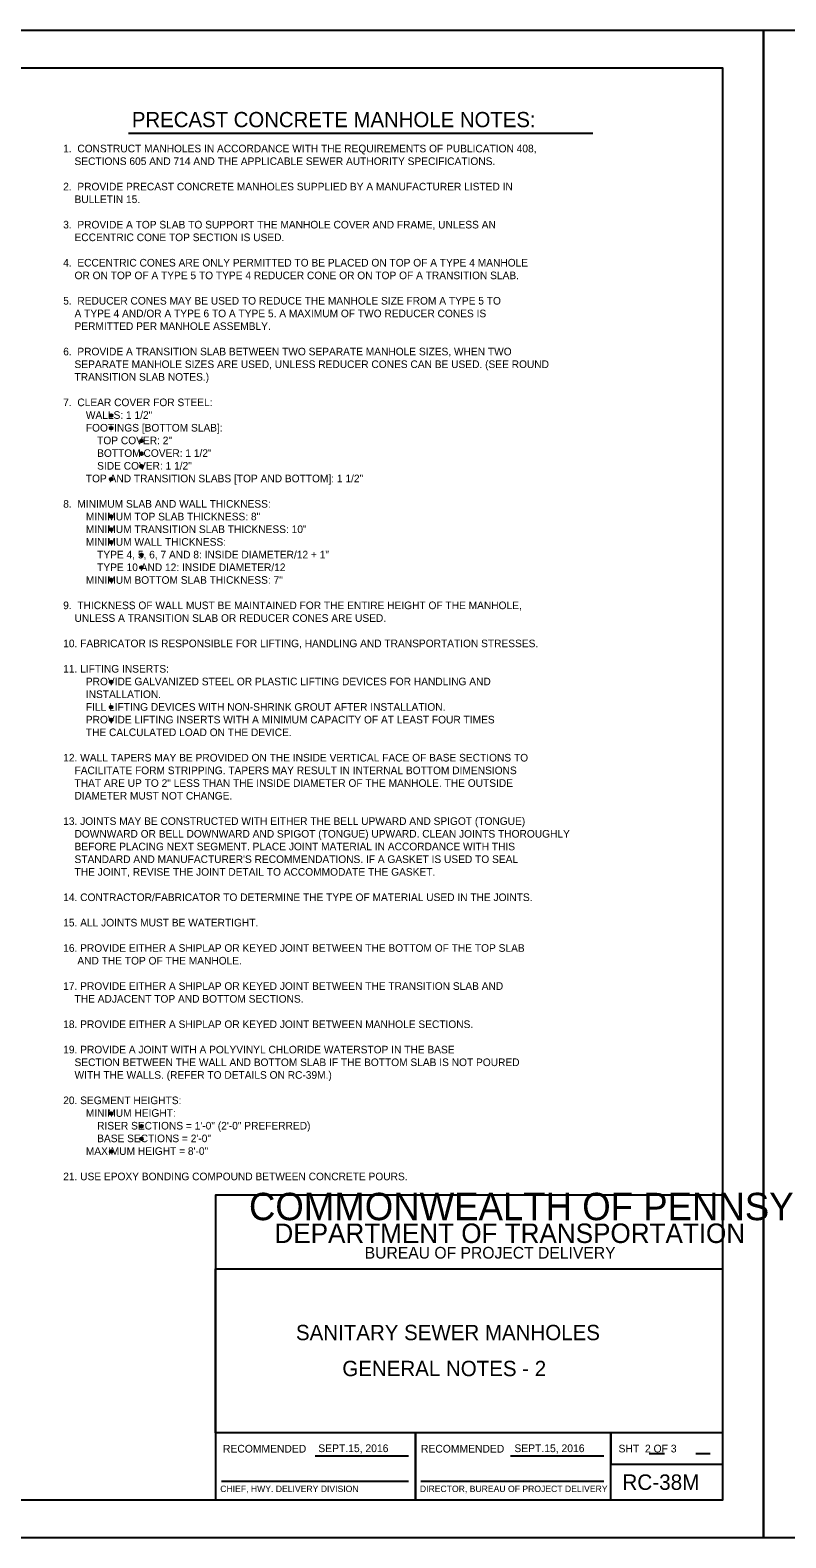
# Model space of a CAD drawing. Extents: x 2106427 to 2114911, y 988717 to 990787.
# Drawn here: x 2110996 to 2111974, y 988839 to 990787 of the extents above; entities that cross this region are included whole.
import ezdxf

# ---------------------------------------------------------------- set-up
doc = ezdxf.new("R2010")
doc.units = 0
for name, color, linetype in [('1', 7, 'Continuous'), ('2', 7, 'Continuous'), ('3', 7, 'Continuous'), ('PLT-BNDY', 7, 'Continuous')]:
    doc.layers.add(name, color=color, linetype=linetype)

msp = doc.modelspace()

# ---------------------------------------------------------------- linework, layer by layer
at = {"layer": '1'}
for p, q in [((2111123.6, 990654.3), (2111724.2, 990654.3)), ((2111365.2, 988944.7), (2111485.6, 988944.7)), ((2111617.8, 988944.7), (2111738.2, 988944.7)), ((2111796.9, 988947.4), (2111817, 988947.4)), ((2111857.3, 988947.4), (2111876.1, 988947.4)), ((2111244.1, 988911.7), (2111485.6, 988911.7)), ((2111501.7, 988911.7), (2111738.2, 988911.7))]:
    msp.add_line(p, q, dxfattribs=at)
msp.add_lwpolyline([(2111892.4, 988887.7), (2111892.4, 990738.1), (2109313.6, 990738.1), (2109313.6, 988887.7), (2111892.4, 988887.7), (2111892.4, 988974.2), (2111236.2, 988974.2), (2111236.2, 989186.4), (2111892.4, 989186.4), (2111892.4, 989281.4), (2111236.2, 989281.4), (2111236.2, 988887.7), (2111494.8, 988887.7), (2111494.8, 988974.2), (2111494.8, 988887.7), (2111747.4, 988887.7), (2111747.4, 988974.2), (2111747.4, 988933.8), (2111892.4, 988933.8)], dxfattribs=at)
for centre, radius in [((2111101.3, 990289.1), 1.75), ((2111101.3, 990272.7), 1.75), ((2111101.3, 990289.1), 1.31), ((2111101.3, 990272.7), 1.31), ((2111101.3, 990289.1), 0.875), ((2111101.3, 990272.7), 0.875), ((2111101.3, 990289.1), 0.437), ((2111101.3, 990272.7), 0.437), ((2111140.4, 990256.3), 1.75), ((2111140.4, 990256.3), 1.31), ((2111140.4, 990256.3), 0.875), ((2111140.4, 990256.3), 0.437), ((2111140.4, 990239.9), 1.75), ((2111140.4, 990239.9), 1.31), ((2111140.4, 990239.9), 0.875), ((2111140.4, 990239.9), 0.437), ((2111140.4, 990223.5), 1.75), ((2111140.4, 990223.5), 1.31), ((2111140.4, 990223.5), 0.875), ((2111140.4, 990223.5), 0.437), ((2111101.3, 990207), 1.75), ((2111101.3, 990207), 1.31), ((2111101.3, 990207), 0.875), ((2111101.3, 990207), 0.437), ((2111101.3, 990158.5), 1.75), ((2111101.3, 990158.5), 1.31), ((2111101.3, 990158.5), 0.875), ((2111101.3, 990158.5), 0.437), ((2111101.3, 990141.8), 1.75), ((2111101.3, 990141.8), 1.31), ((2111101.3, 990141.8), 0.875), ((2111101.3, 990141.8), 0.437), ((2111101.3, 990125.4), 1.75), ((2111101.3, 990125.4), 1.31), ((2111101.3, 990125.4), 0.875), ((2111101.3, 990125.4), 0.437), ((2111140.4, 990108.9), 1.75), ((2111140.4, 990108.9), 1.31), ((2111140.4, 990108.9), 0.875), ((2111140.4, 990108.9), 0.437), ((2111101.3, 990076.6), 1.75), ((2111140.4, 990092.6), 1.75), ((2111140.4, 990092.6), 1.31), ((2111140.4, 990092.6), 0.875), ((2111140.4, 990092.6), 0.437), ((2111101.3, 990076.6), 1.31), ((2111101.3, 990076.6), 0.875), ((2111101.3, 990076.6), 0.437), ((2111101.3, 989945.1), 1.75), ((2111101.3, 989945.1), 1.31), ((2111101.3, 989945.1), 0.875), ((2111101.3, 989945.1), 0.437), ((2111101.3, 989912.3), 1.75), ((2111101.3, 989912.3), 1.31), ((2111101.3, 989912.3), 0.875), ((2111101.3, 989912.3), 0.437), ((2111101.3, 989895.9), 1.75), ((2111101.3, 989895.9), 1.31), ((2111101.3, 989895.9), 0.875), ((2111101.3, 989895.9), 0.437), ((2111101.3, 989386.9), 1.75), ((2111101.3, 989386.9), 1.31), ((2111101.3, 989386.9), 0.875), ((2111101.3, 989386.9), 0.437), ((2111140.4, 989370.7), 1.75), ((2111140.4, 989370.7), 1.31), ((2111140.4, 989370.7), 0.875), ((2111140.4, 989370.7), 0.437), ((2111101.3, 989337.7), 1.75), ((2111101.3, 989337.7), 1.31), ((2111101.3, 989337.7), 0.875), ((2111101.3, 989337.7), 0.437), ((2111140.4, 989354.1), 1.75), ((2111140.4, 989354.1), 1.31), ((2111140.4, 989354.1), 0.875), ((2111140.4, 989354.1), 0.437)]:
    msp.add_circle(centre, radius, dxfattribs=at)
at = {"layer": 'PLT-BNDY'}
for points in [[(2109185.7, 990787.3), (2111944.9, 990787.3), (2111944.9, 988838.5), (2109185.7, 988838.5)], [(2111944.9, 990787.3), (2114704.1, 990787.3), (2114704.1, 988838.5), (2111944.9, 988838.5)]]:
    msp.add_lwpolyline(points, close=True, dxfattribs=at)

# ---------------------------------------------------------------- texts
at = {"layer": '1'}
msp.add_text('SANITARY SEWER MANHOLES', height=19.816, dxfattribs=at).set_placement((2111340.2, 989094))
at = {"layer": '2'}
msp.add_text('GENERAL NOTES - 2', height=19.816, dxfattribs=at).set_placement((2111400.2, 989047.5))
at = {"layer": '3'}
for s, height, p in [('PRECAST CONCRETE MANHOLE NOTES:', 19.685, (2111128, 990661.9)), ('1.  CONSTRUCT MANHOLES IN ACCORDANCE WITH THE REQUIREMENTS OF PUBLICATION 408,', 9.843, (2111039.2, 990629.4)), ('    SECTIONS 605 AND 714 AND THE APPLICABLE SEWER AUTHORITY SPECIFICATIONS. ', 9.843, (2111039.2, 990613)), ('2.  PROVIDE PRECAST CONCRETE MANHOLES SUPPLIED BY A MANUFACTURER LISTED IN', 9.843, (2111039.2, 990580.2)), ('    BULLETIN 15.', 9.843, (2111039.2, 990563.8)), ('3.  PROVIDE A TOP SLAB TO SUPPORT THE MANHOLE COVER AND FRAME, UNLESS AN', 9.843, (2111039.2, 990531)), ('    ECCENTRIC CONE TOP SECTION IS USED.', 9.843, (2111039.2, 990514.6)), ('4.  ECCENTRIC CONES ARE ONLY PERMITTED TO BE PLACED ON TOP OF A TYPE 4 MANHOLE', 9.843, (2111039.2, 990481.8)), ('    OR ON TOP OF A TYPE 5 TO TYPE 4 REDUCER CONE OR ON TOP OF A TRANSITION SLAB.', 9.843, (2111039.2, 990465.4)), ('5.  REDUCER CONES MAY BE USED TO REDUCE THE MANHOLE SIZE FROM A TYPE 5 TO', 9.843, (2111039.2, 990432.6)), ('    A TYPE 4 AND/OR A TYPE 6 TO A TYPE 5. A MAXIMUM OF TWO REDUCER CONES IS', 9.843, (2111039.2, 990416.2)), ('    PERMITTED PER MANHOLE ASSEMBLY.', 9.843, (2111039.2, 990399.8)), ('6.  PROVIDE A TRANSITION SLAB BETWEEN TWO SEPARATE MANHOLE SIZES, WHEN TWO', 9.843, (2111039.2, 990367)), ('    SEPARATE MANHOLE SIZES ARE USED, UNLESS REDUCER CONES CAN BE USED. (SEE ROUND', 9.843, (2111039.2, 990350.6)), ('    TRANSITION SLAB NOTES.) ', 9.843, (2111039.2, 990334.2)), ('7.  CLEAR COVER FOR STEEL:', 9.843, (2111039.2, 990301.3)), ('        WALLS: 1 1/2"', 9.843, (2111039.2, 990284.9)), ('        FOOTINGS [BOTTOM SLAB]:', 9.843, (2111039.2, 990268.5)), ('            TOP COVER: 2"', 9.843, (2111039.2, 990252.1)), ('            BOTTOM COVER: 1 1/2"', 9.843, (2111039.2, 990235.7)), ('            SIDE COVER: 1 1/2"', 9.843, (2111039.2, 990219.3)), ('        TOP AND TRANSITION SLABS [TOP AND BOTTOM]: 1 1/2"', 9.843, (2111039.2, 990202.9)), ('8.  MINIMUM SLAB AND WALL THICKNESS:', 9.843, (2111039.2, 990170.1)), ('        MINIMUM TOP SLAB THICKNESS: 8"', 9.843, (2111039.2, 990153.7)), ('        MINIMUM TRANSITION SLAB THICKNESS: 10"', 9.843, (2111039.2, 990137.3)), ('        MINIMUM WALL THICKNESS:', 9.843, (2111039.2, 990120.9)), ('            TYPE 4, 5, 6, 7 AND 8: INSIDE DIAMETER/12 + 1"', 9.843, (2111039.2, 990104.5)), ('            TYPE 10 AND 12: INSIDE DIAMETER/12', 9.843, (2111039.2, 990088.1)), ('        MINIMUM BOTTOM SLAB THICKNESS: 7"', 9.843, (2111039.2, 990071.7)), ('9.  THICKNESS OF WALL MUST BE MAINTAINED FOR THE ENTIRE HEIGHT OF THE MANHOLE,', 9.843, (2111039.2, 990038.9)), ('    UNLESS A TRANSITION SLAB OR REDUCER CONES ARE USED.', 9.843, (2111039.2, 990022.5)), ('10. FABRICATOR IS RESPONSIBLE FOR LIFTING, HANDLING AND TRANSPORTATION STRESSES.', 9.843, (2111039.2, 989989.7)), ('11. LIFTING INSERTS:', 9.843, (2111039.2, 989956.9)), ('        PROVIDE GALVANIZED STEEL OR PLASTIC LIFTING DEVICES FOR HANDLING AND', 9.843, (2111039.2, 989940.5)), ('        INSTALLATION.', 9.843, (2111039.2, 989924)), ('        FILL LIFTING DEVICES WITH NON-SHRINK GROUT AFTER INSTALLATION.', 9.843, (2111039.2, 989907.6)), ('        THE CALCULATED LOAD ON THE DEVICE.', 9.843, (2111039.2, 989874.8)), ('        PROVIDE LIFTING INSERTS WITH A MINIMUM CAPACITY OF AT LEAST FOUR TIMES', 9.843, (2111039.2, 989891.2)), ('12. WALL TAPERS MAY BE PROVIDED ON THE INSIDE VERTICAL FACE OF BASE SECTIONS TO', 9.843, (2111039.2, 989842)), ('    FACILITATE FORM STRIPPING. TAPERS MAY RESULT IN INTERNAL BOTTOM DIMENSIONS', 9.843, (2111039.2, 989825.6)), ('    THAT ARE UP TO 2" LESS THAN THE INSIDE DIAMETER OF THE MANHOLE. THE OUTSIDE', 9.843, (2111039.2, 989809.2)), ('    DIAMETER MUST NOT CHANGE.', 9.843, (2111039.2, 989792.8)), ('13. JOINTS MAY BE CONSTRUCTED WITH EITHER THE BELL UPWARD AND SPIGOT (TONGUE)', 9.843, (2111039.2, 989760)), ('    DOWNWARD OR BELL DOWNWARD AND SPIGOT (TONGUE) UPWARD. CLEAN JOINTS THOROUGHLY', 9.843, (2111039.2, 989743.6)), ('    BEFORE PLACING NEXT SEGMENT. PLACE JOINT MATERIAL IN ACCORDANCE WITH THIS', 9.843, (2111039.2, 989727.2)), ("    STANDARD AND MANUFACTURER'S RECOMMENDATIONS. IF A GASKET IS USED TO SEAL", 9.843, (2111039.2, 989710.8)), ('    THE JOINT, REVISE THE JOINT DETAIL TO ACCOMMODATE THE GASKET.', 9.843, (2111039.2, 989694.4)), ('14. CONTRACTOR/FABRICATOR TO DETERMINE THE TYPE OF MATERIAL USED IN THE JOINTS.', 9.843, (2111039.2, 989661.6)), ('15. ALL JOINTS MUST BE WATERTIGHT.', 9.843, (2111039.2, 989628.8)), ('16. PROVIDE EITHER A SHIPLAP OR KEYED JOINT BETWEEN THE BOTTOM OF THE TOP SLAB', 9.843, (2111039.2, 989596)), ('     AND THE TOP OF THE MANHOLE.', 9.843, (2111039.2, 989579.6)), ('17. PROVIDE EITHER A SHIPLAP OR KEYED JOINT BETWEEN THE TRANSITION SLAB AND', 9.843, (2111039.2, 989546.8)), ('    THE ADJACENT TOP AND BOTTOM SECTIONS.', 9.843, (2111039.2, 989530.3)), ('18. PROVIDE EITHER A SHIPLAP OR KEYED JOINT BETWEEN MANHOLE SECTIONS.', 9.843, (2111039.2, 989497.5)), ('19. PROVIDE A JOINT WITH A POLYVINYL CHLORIDE WATERSTOP IN THE BASE ', 9.843, (2111039.2, 989464.7)), ('    SECTION BETWEEN THE WALL AND BOTTOM SLAB IF THE BOTTOM SLAB IS NOT POURED ', 9.843, (2111039.2, 989448.3)), ('    WITH THE WALLS. (REFER TO DETAILS ON RC-39M.)', 9.843, (2111039.2, 989431.9)), ('20. SEGMENT HEIGHTS:', 9.843, (2111039.2, 989399.1)), ('        MINIMUM HEIGHT:', 9.843, (2111039.2, 989382.7)), ('            RISER SECTIONS = 1\'-0" (2\'-0" PREFERRED)', 9.843, (2111039.2, 989366.3)), ('            BASE SECTIONS = 2\'-0"', 9.843, (2111039.2, 989349.9)), ('        MAXIMUM HEIGHT = 8\'-0"', 9.843, (2111039.2, 989333.5)), ('21. USE EPOXY BONDING COMPOUND BETWEEN CONCRETE POURS.', 9.843, (2111039.2, 989300.7)), ('COMMONWEALTH OF PENNSYLVANIA', 35.379, (2111279.4, 989249.1)), ('DEPARTMENT OF TRANSPORTATION', 25.211, (2111312.4, 989219.6)), ('BUREAU OF PROJECT DELIVERY', 15.164, (2111429.1, 989199.4)), ('RECOMMENDED', 10, (2111245.8, 988948.7)), ('SEPT.15, 2016', 10, (2111369.1, 988949.3)), ('RECOMMENDED', 10, (2111501.9, 988948.7)), ('SEPT.15, 2016', 10, (2111622.7, 988949.3)), ('SHT  2 OF 3', 10, (2111757.4, 988948.9)), ('RC-38M', 20, (2111762.4, 988900.5)), ('CHIEF, HWY. DELIVERY DIVISION', 8.333, (2111242.3, 988897.7)), ('DIRECTOR, BUREAU OF PROJECT DELIVERY', 8.333, (2111500.5, 988897.7))]:
    msp.add_text(s, height=height, dxfattribs=at).set_placement(p)

doc.saveas('drawing.dxf')
